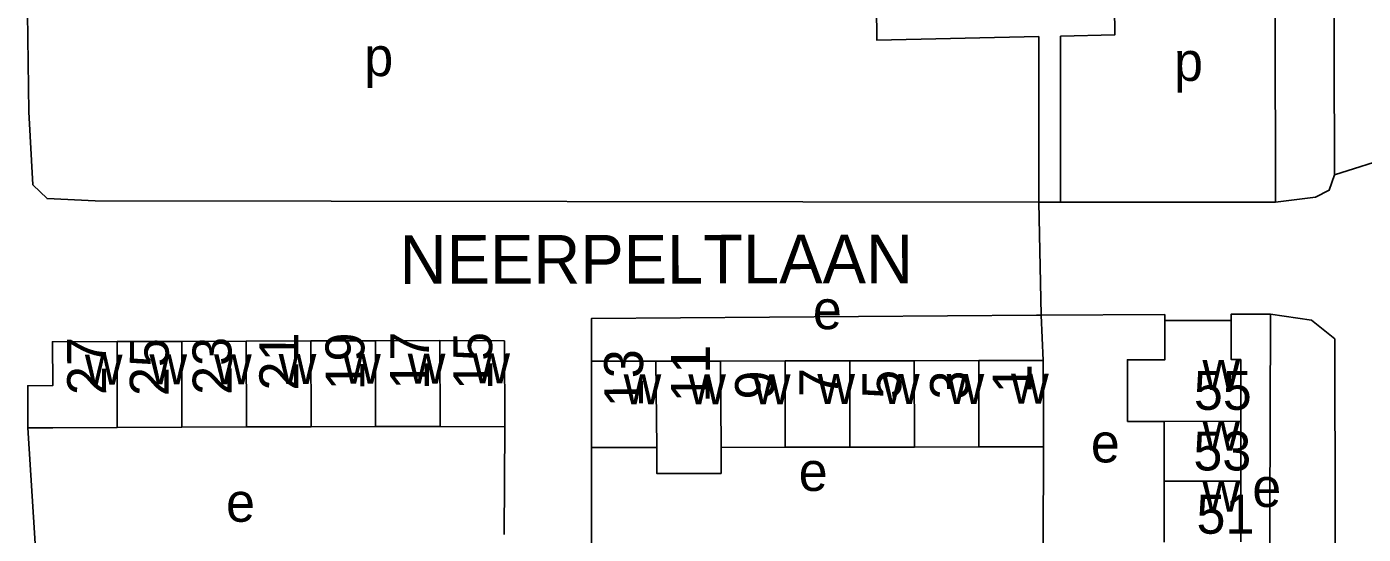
# Model space of a CAD drawing. Extents: x 159675 to 162108, y 386471 to 388472.
# Drawn here: x 161166.2 to 161303.6, y 388027.1 to 388079.2 of the extents above; entities that cross this region are included whole.
import ezdxf

# ---------------------------------------------------------------- set-up
doc = ezdxf.new("R2010")
doc.units = 0
for name, color, linetype in [('BLT_Basislijn', 7, 'Continuous'), ('BLT_Bebouwing', 7, 'Continuous'), ('BLT_Centroide', 7, 'Continuous'), ('BLT_Huisnummer', 7, 'Continuous'), ('BLT_Huisnummer_ tussenligend', 7, 'Continuous'), ('BLT_Onderverdeling_panden', 7, 'Continuous'), ('BLT_Straatnaam', 7, 'Continuous'), ('BLT_Vlakafsluiter', 7, 'Continuous')]:
    doc.layers.add(name, color=color, linetype=linetype)

msp = doc.modelspace()

# ---------------------------------------------------------------- linework, layer by layer
at = {"layer": 'BLT_Basislijn'}
for p, q in [((161270.24, 388078.22), (161270.24, 388061.22)), ((161272.47, 388078.27), (161272.47, 388061.22)), ((161270.24, 388061.22), (161272.47, 388061.22)), ((161270.69, 388044.93), (161270.47, 388049.6)), ((161167.29, 388022.86), (161166.32, 388038.02)), ((161215.35, 388038.13), (161215.27, 388027.04)), ((161224.26, 388025.87), (161224.26, 388035.98)), ((161270.68, 388026.09), (161270.7, 388036.05))]:
    msp.add_line(p, q, dxfattribs=at)
for points in [[(161294.17, 388141.26), (161297.93, 388141.15), (161299.73, 388140.69), (161300.43, 388139.6), (161300.63, 388064)], [(161248.07, 388084.59), (161247.78, 388084.01), (161220.36, 388083.68), (161220.08, 388089.37), (161219.86, 388089.53), (161168.17, 388089.37), (161166.36, 388087.38), (161166.2, 388085.75), (161166.41, 388070.5), (161166.83, 388062.99), (161168.29, 388061.57), (161173.23, 388061.33), (161270.24, 388061.22)], [(161272.47, 388089.93), (161277.92, 388089.98), (161278.03, 388078.39), (161272.47, 388078.27)], [(161270.24, 388078.22), (161253.57, 388077.86), (161253.5, 388084.95)], [(161294.57, 388061.19), (161294.52, 388080.22)], [(161300.63, 388064), (161300.07, 388062.43), (161298.66, 388061.71), (161294.57, 388061.19)], [(161272.47, 388061.22), (161294.57, 388061.19)], [(161270.47, 388049.6), (161269.98, 388049.59), (161224.25, 388049.24), (161224.24, 388044.86)], [(161270.47, 388049.6), (161283.17, 388049.65), (161283.18, 388049.05)], [(161290, 388049.06), (161290, 388049.68), (161294.03, 388049.7)], [(161294.03, 388049.7), (161293.92, 388007.71)], [(161294.03, 388049.7), (161298.25, 388049.09), (161300.65, 388047.16), (161300.74, 388009.28), (161298.29, 388007.86), (161293.92, 388007.71)]]:
    msp.add_lwpolyline(points, dxfattribs=at)
at = {"layer": 'BLT_Bebouwing'}
for p, q in [((161283.18, 388049.05), (161290, 388049.06)), ((161182.13, 388046.9), (161175.49, 388046.88)), ((161188.76, 388046.92), (161182.13, 388046.9)), ((161195.4, 388046.94), (161188.76, 388046.92)), ((161202.04, 388046.96), (161195.4, 388046.94)), ((161208.68, 388046.98), (161202.04, 388046.96)), ((161224.24, 388044.86), (161224.26, 388035.98)), ((161230.88, 388044.86), (161224.24, 388044.86)), ((161237.51, 388044.88), (161230.88, 388044.86)), ((161244.15, 388044.89), (161237.51, 388044.88)), ((161250.79, 388044.9), (161244.15, 388044.89)), ((161257.42, 388044.91), (161250.79, 388044.9)), ((161264.06, 388044.92), (161257.42, 388044.91)), ((161270.69, 388044.93), (161264.06, 388044.92)), ((161168.88, 388038.03), (161175.51, 388038.06)), ((161175.51, 388038.06), (161182.15, 388038.08)), ((161182.15, 388038.08), (161188.79, 388038.1)), ((161188.79, 388038.1), (161195.43, 388038.12)), ((161195.43, 388038.12), (161202.06, 388038.14)), ((161202.06, 388038.14), (161208.7, 388038.15)), ((161208.7, 388038.15), (161215.35, 388038.13)), ((161283.12, 388032.53), (161283.11, 388038.68)), ((161291, 388038.69), (161291, 388032.53)), ((161237.58, 388036), (161244.16, 388036.02)), ((161244.16, 388036.02), (161250.8, 388036.03)), ((161250.8, 388036.03), (161257.44, 388036.04)), ((161257.44, 388036.04), (161264.07, 388036.05)), ((161264.07, 388036.05), (161270.7, 388036.05)), ((161283.12, 388026.28), (161283.12, 388032.53)), ((161291, 388032.53), (161291.01, 388026.29))]:
    msp.add_line(p, q, dxfattribs=at)
for points in [[(161283.11, 388038.68), (161279.35, 388038.68), (161279.34, 388045.01), (161283.17, 388044.99), (161283.18, 388049.05)], [(161290, 388049.06), (161290.01, 388045.02), (161290.99, 388045.02), (161291, 388038.69)], [(161175.49, 388046.88), (161168.85, 388046.86), (161168.87, 388042.35), (161166.31, 388042.34), (161166.32, 388038.02)], [(161215.35, 388038.13), (161215.31, 388046.95), (161208.68, 388046.98)], [(161270.7, 388036.05), (161270.7, 388039.93), (161270.69, 388044.93)], [(161166.32, 388038.02), (161168.88, 388038.03)], [(161224.26, 388035.98), (161229.26, 388035.99), (161230.98, 388036)], [(161230.98, 388036), (161230.98, 388033.32), (161237.58, 388033.33), (161237.58, 388036)]]:
    msp.add_lwpolyline(points, dxfattribs=at)
at = {"layer": 'BLT_Onderverdeling_panden'}
for p, q in [((161175.51, 388038.06), (161175.49, 388046.88)), ((161182.15, 388038.08), (161182.13, 388046.9)), ((161188.79, 388038.1), (161188.76, 388046.92)), ((161195.43, 388038.12), (161195.4, 388046.94)), ((161202.06, 388038.14), (161202.04, 388046.96)), ((161208.7, 388038.15), (161208.68, 388046.98)), ((161230.98, 388036), (161230.88, 388044.86)), ((161237.58, 388036), (161237.51, 388044.88)), ((161244.16, 388036.02), (161244.15, 388044.89)), ((161250.8, 388036.03), (161250.79, 388044.9)), ((161257.44, 388036.04), (161257.42, 388044.91)), ((161264.07, 388036.05), (161264.06, 388044.92)), ((161283.11, 388038.68), (161291, 388038.69)), ((161283.12, 388032.53), (161291, 388032.53))]:
    msp.add_line(p, q, dxfattribs=at)
at = {"layer": 'BLT_Vlakafsluiter'}
for p, q in [((161312.55, 388067.8), (161300.63, 388064)), ((161270.24, 388061.22), (161270.47, 388049.6))]:
    msp.add_line(p, q, dxfattribs=at)

# ---------------------------------------------------------------- texts
at = {"layer": 'BLT_Centroide'}
for s, p in [('p', (161200.9, 388074.16)), ('p', (161284.13, 388073.67)), ('e', (161247.01, 388048.15)), ('w', (161172.18, 388042.46)), ('w', (161178.82, 388042.49)), ('w', (161185.46, 388042.49)), ('w', (161192.1, 388042.52)), ('w', (161198.73, 388042.54)), ('w', (161205.37, 388042.55)), ('w', (161212.01, 388042.59)), ('w', (161287.05, 388041.91)), ('w', (161227.56, 388040.44)), ('w', (161234.2, 388040.44)), ('w', (161240.84, 388040.44)), ('w', (161247.47, 388040.47)), ('w', (161254.11, 388040.47)), ('w', (161260.75, 388040.47)), ('w', (161267.38, 388040.5)), ('w', (161287.05, 388035.66)), ('e', (161275.58, 388034.46)), ('e', (161245.55, 388031.53)), ('w', (161287.06, 388029.41)), ('e', (161292.17, 388029.88)), ('e', (161186.69, 388028.36))]:
    msp.add_text(s, height=4, dxfattribs=at).set_placement(p)
at = {"layer": 'BLT_Huisnummer'}
for s, rotation, p in [('19', 90.1624, (161200.92, 388041.86)), ('15', 90.1624, (161214.06, 388041.92)), ('27', 90.1624, (161174.37, 388041.39)), ('23', 90.1624, (161187.26, 388041.41)), ('13', 90.0888, (161229.56, 388040.14)), ('9', 90.0888, (161243.02, 388040.93)), ('5', 90.0888, (161256.09, 388041)), ('1', 90.0888, (161269.5, 388041.57)), ('55', 0.0654, (161286.17, 388039.86))]:
    msp.add_text(s, height=4, rotation=rotation, dxfattribs=at).set_placement(p)
at = {"layer": 'BLT_Huisnummer_ tussenligend'}
for s, rotation, p in [('21', 89.8369, (161194.11, 388041.85)), ('17', 89.8369, (161207.55, 388041.92)), ('25', 89.8369, (161180.79, 388041.27)), ('11', 89.8642, (161236.41, 388040.61)), ('7', 89.8642, (161249.6, 388041.16)), ('3', 89.8642, (161263.05, 388040.92)), ('53', 0.0654, (161286.12, 388033.63)), ('51', 0.0654, (161286.44, 388027.13))]:
    msp.add_text(s, height=4, rotation=rotation, dxfattribs=at).set_placement(p)
at = {"layer": 'BLT_Straatnaam'}
msp.add_text('NEERPELTLAAN', height=5, rotation=0.0667, dxfattribs=at).set_placement((161204.53, 388052.81))

doc.saveas('drawing.dxf')
